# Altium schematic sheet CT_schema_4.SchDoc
size 578 x 363 mm
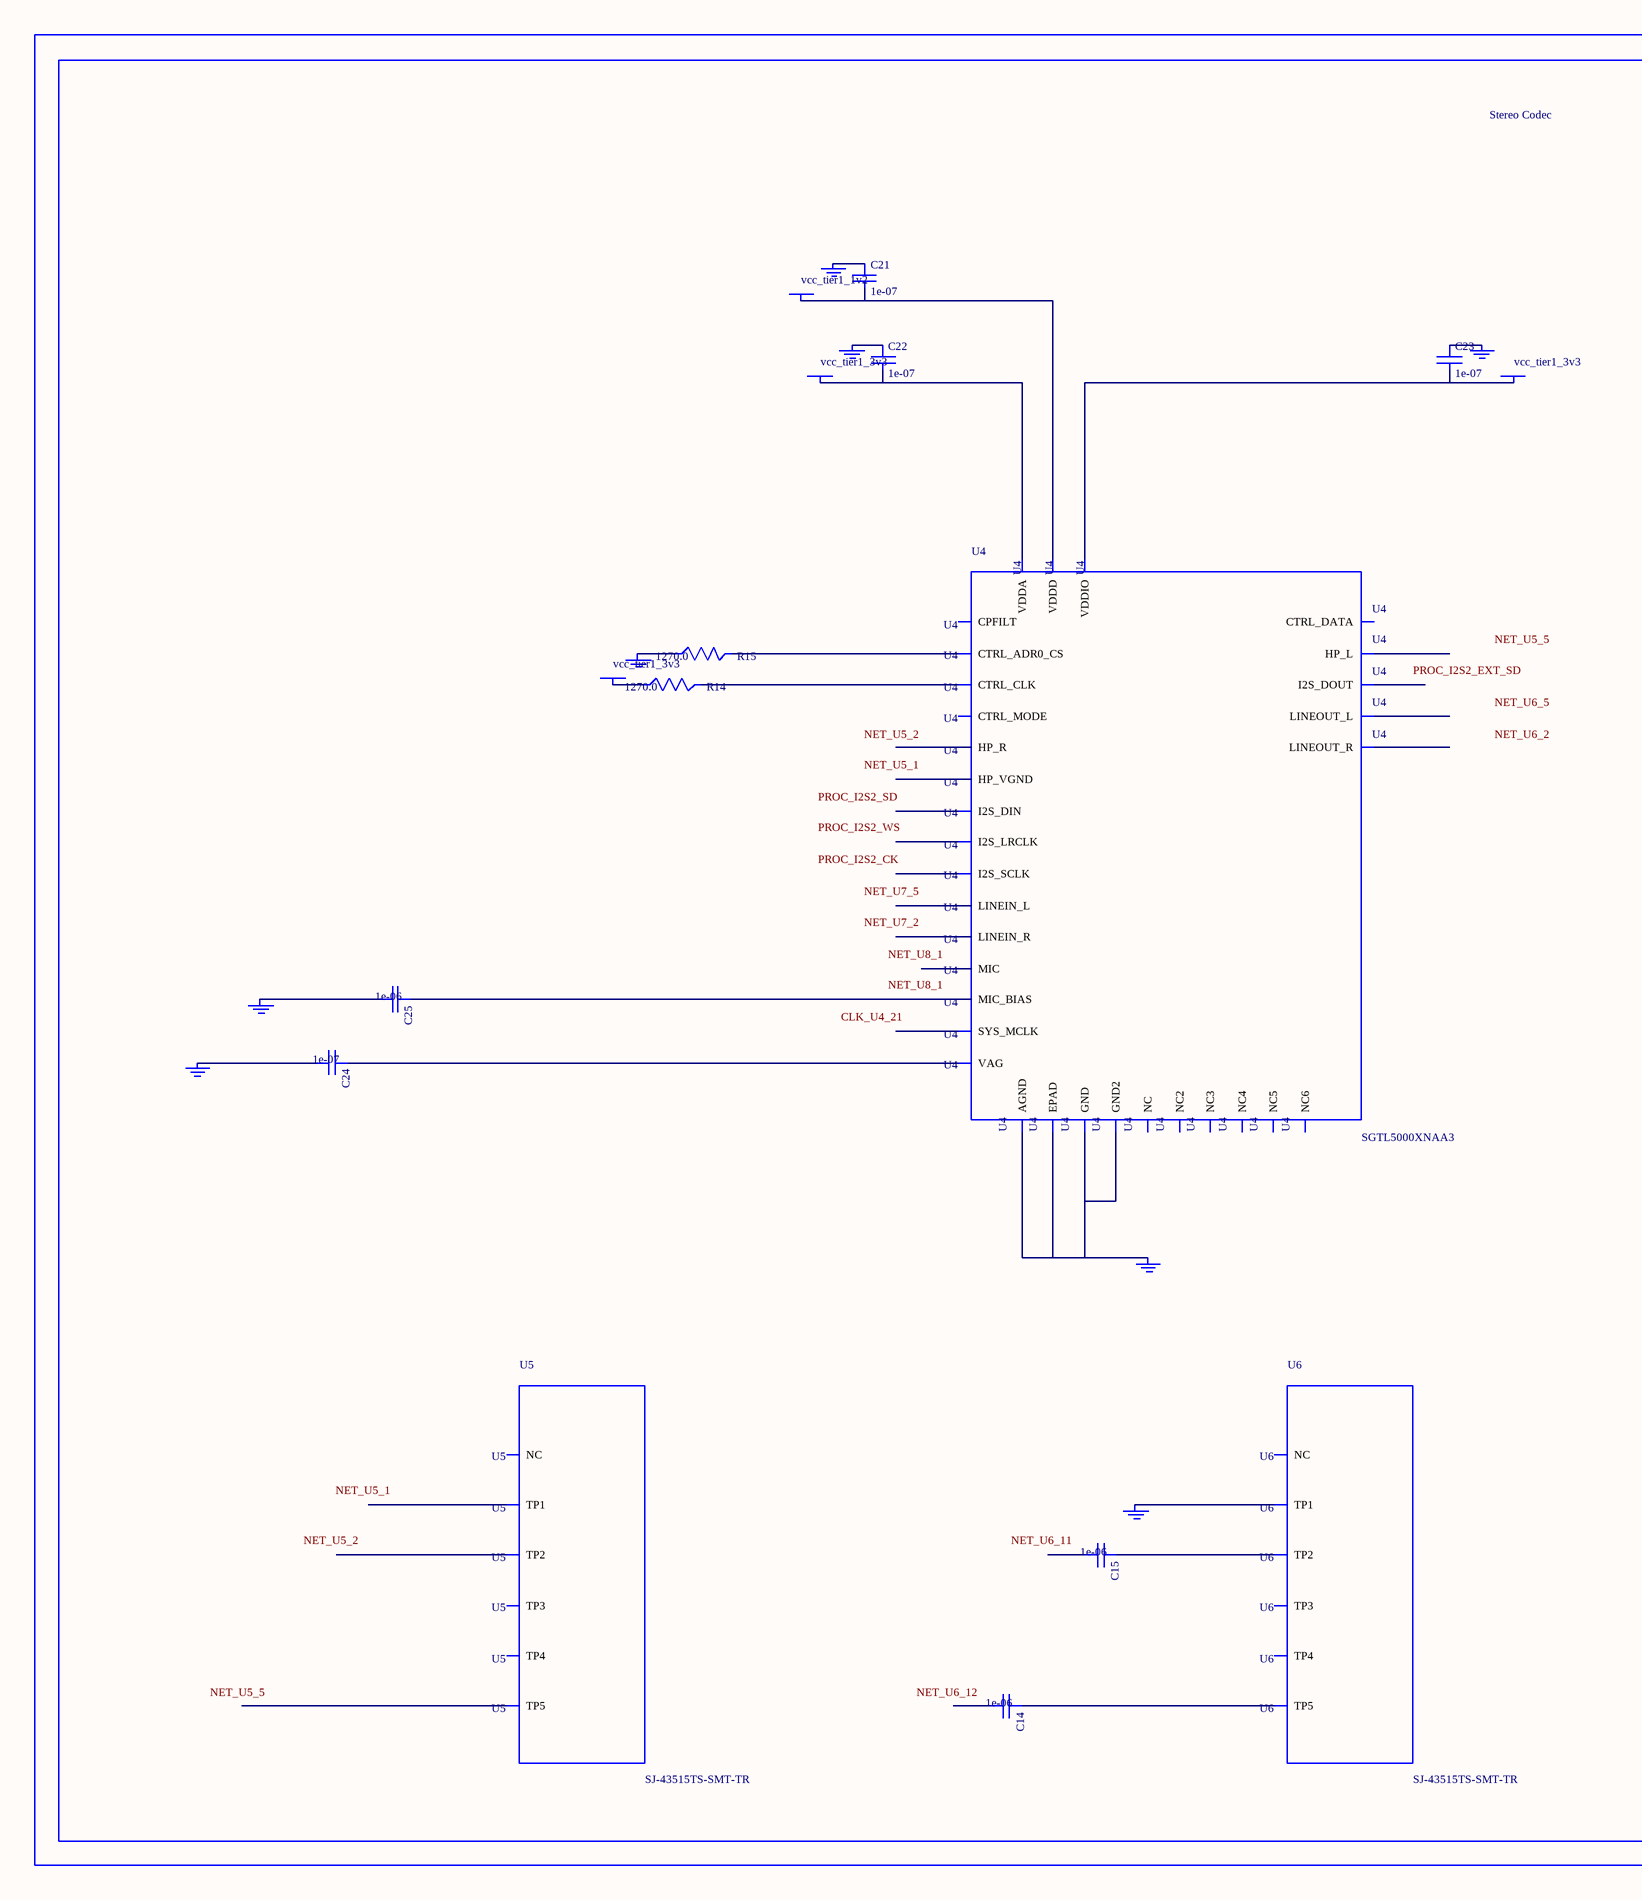
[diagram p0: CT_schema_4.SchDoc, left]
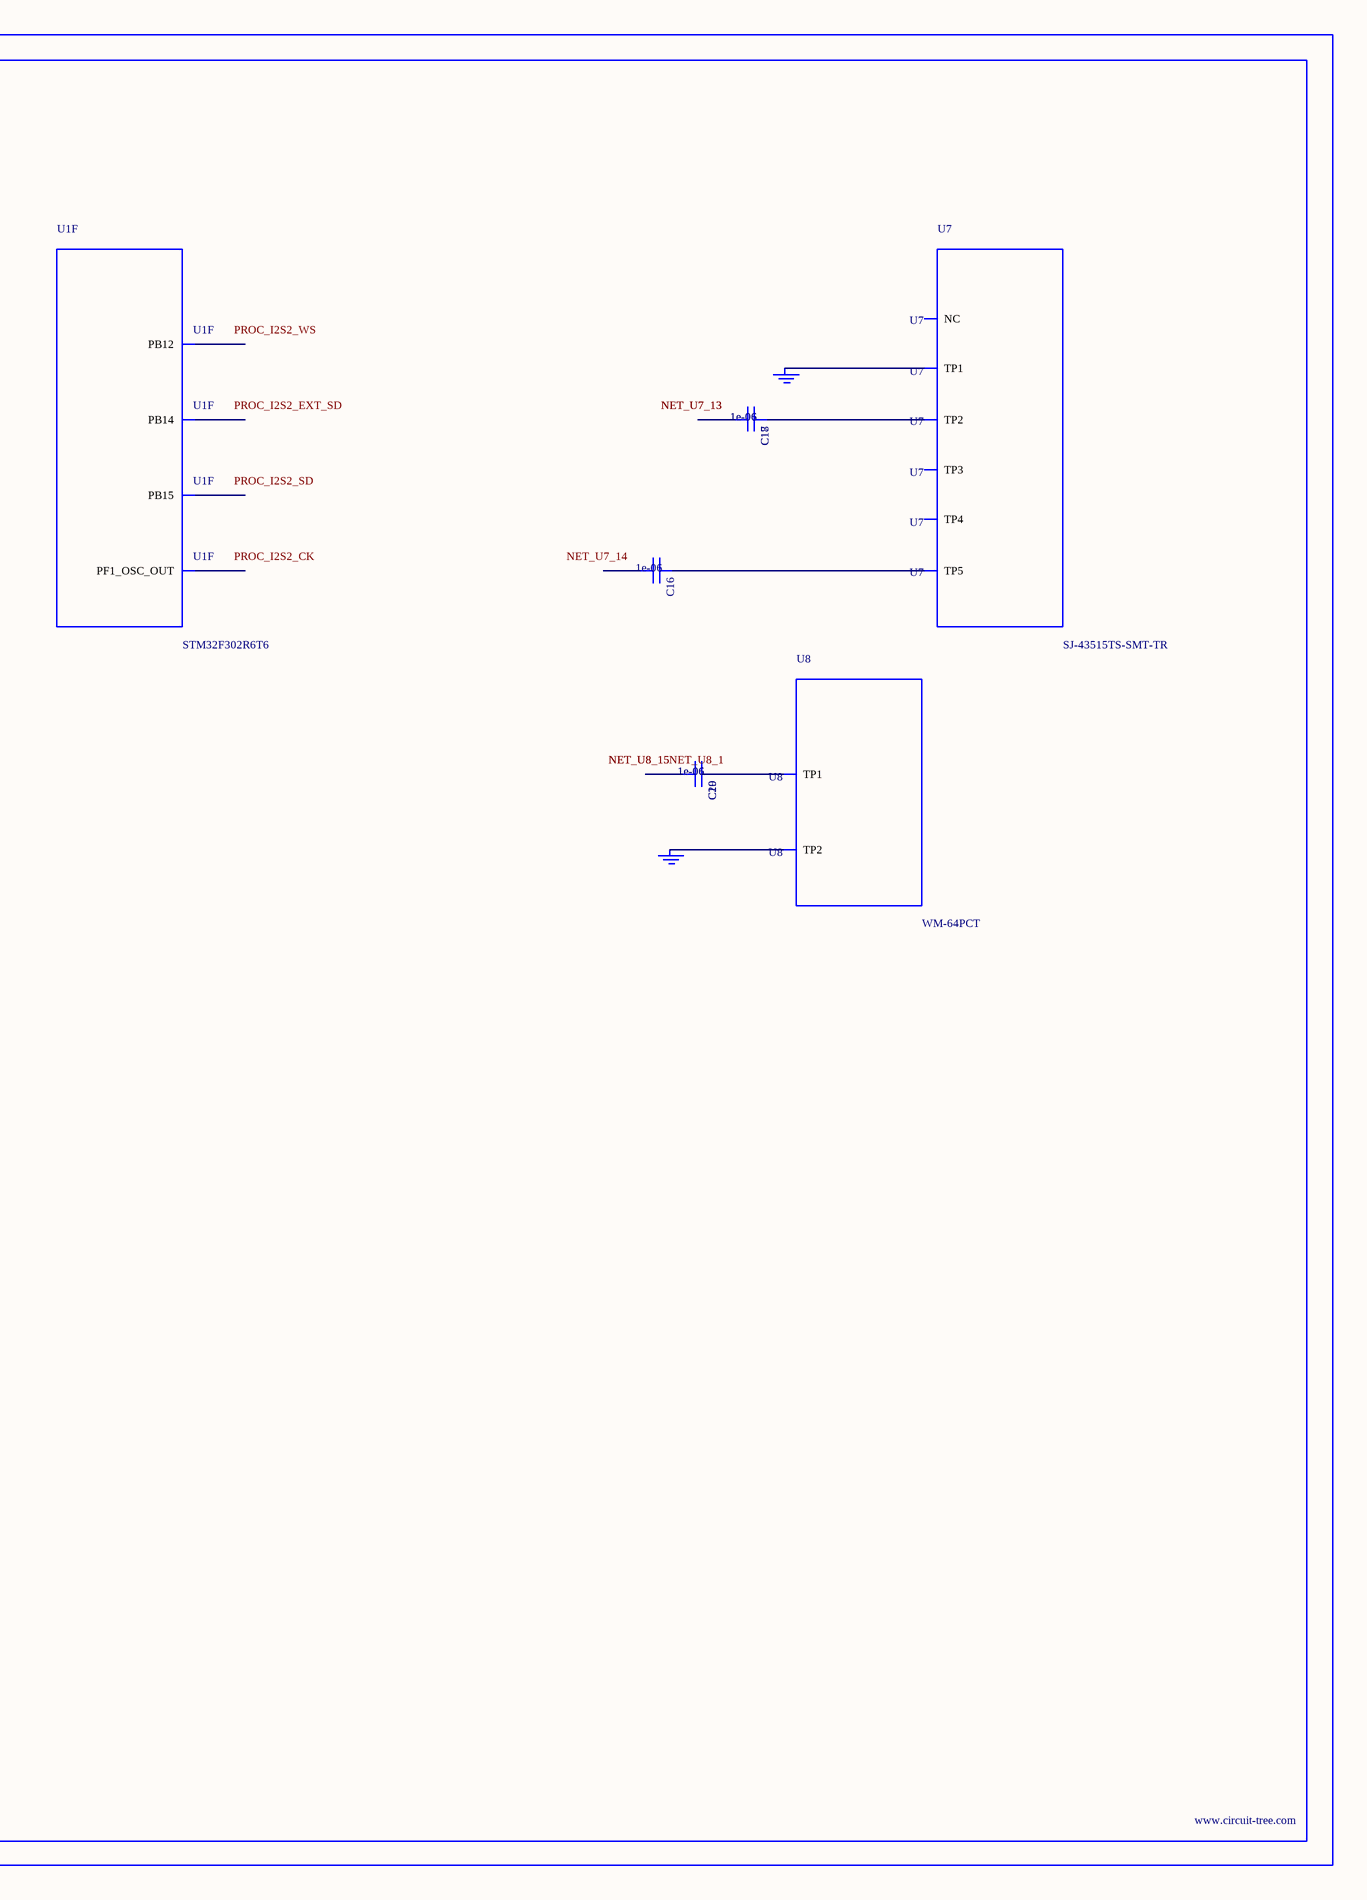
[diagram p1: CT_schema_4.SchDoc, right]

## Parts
BORDER3  (no value)
C14  1e-06  [C0603]
C15  1e-06  [C0603]
C16  1e-06  [C0603]
C17  1e-06  [C0603]
C18  1e-06  [C0603]
C19  1e-06  [C0603]
C20  1e-06  [C0603]
C21  1e-07  [C0402]
C22  1e-07  [C0402]
C23  1e-07  [C0402]
C24  1e-07  [C0402]
C25  1e-06  [C0603]
GND_INSTANCE_3_0  (no value)
GND_INSTANCE_3_1  (no value)
GND_INSTANCE_3_2  (no value)
GND_INSTANCE_3_3  (no value)
GND_INSTANCE_3_4  (no value)
GND_INSTANCE_3_5  (no value)
GND_INSTANCE_3_6  (no value)
GND_INSTANCE_3_7  (no value)
GND_INSTANCE_3_8  (no value)
GND_INSTANCE_3_9  (no value)
GND_INSTANCE_3_10  (no value)
POWER_INSTANCE_3_0  vcc_tier1_3v3
POWER_INSTANCE_3_1  vcc_tier1_3v3
POWER_INSTANCE_3_2  vcc_tier1_3v3
POWER_INSTANCE_3_3  vcc_tier1_1v2
R14  1270.0  [R0603]
R15  1270.0  [R0603]
U1  STM32F302R6T6  [LQFP64]  (part F of 7)
U4  SGTL5000XNAA3  [QFN-32]
U5  SJ-43515TS-SMT-TR  [SJ-43515TS-SMT-TR]
U6  SJ-43515TS-SMT-TR  [SJ-43515TS-SMT-TR]
U7  SJ-43515TS-SMT-TR  [SJ-43515TS-SMT-TR]
U8  WM-64PCT  [WM-64PC]

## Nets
NetC14_1: C14.1 U6.5(TP5)
NetC15_1: C15.1 U6.2(TP2)
NetC16_1: C16.1 U7.5(TP5)
NetC17_1: C17.1 C18.1 U7.2(TP2)
NetC17_2: C17.2 C18.2
NetC19_1: C19.1 C20.1 U8.1(TP1)
NetC19_2: C19.2 C20.2
NetC21_1: C21.1 GND_INSTANCE_3_5.0(GND)
NetC21_2: C21.2 POWER_INSTANCE_3_3.0(PWR) U4.30(VDDD)
NetC22_1: C22.1 GND_INSTANCE_3_1.0(GND)
NetC22_2: C22.2 POWER_INSTANCE_3_0.0(PWR) U4.5(VDDA)
NetC23_1: C23.1 GND_INSTANCE_3_4.0(GND)
NetC23_2: C23.2 POWER_INSTANCE_3_1.0(PWR) U4.20(VDDIO)
NetC24_1: C24.1 U4.10(VAG)
NetC24_2: C24.2 GND_INSTANCE_3_2.0(GND)
NetC25_1: C25.1 U4.16(MIC_BIAS)
NetC25_2: C25.2 GND_INSTANCE_3_3.0(GND)
NetGND_INSTANCE_3_0_0: GND_INSTANCE_3_0.0(GND) U4.1(GND) U4.3(GND2) U4.7(AGND) U4.EXP(EPAD)
NetGND_INSTANCE_3_6_0: GND_INSTANCE_3_6.0(GND) R15.1
NetGND_INSTANCE_3_7_0: GND_INSTANCE_3_7.0(GND) U6.1(TP1)
NetGND_INSTANCE_3_8_0: GND_INSTANCE_3_8.0(GND) GND_INSTANCE_3_9.0(GND) U7.1(TP1)
NetGND_INSTANCE_3_10_0: GND_INSTANCE_3_10.0(GND) U8.2(TP2)
NetPOWER_INSTANCE_3_2_0: POWER_INSTANCE_3_2.0(PWR) R14.1
NetR14_2: R14.2 U4.29(CTRL_CLK)
NetR15_2: R15.2 U4.31(CTRL_ADR0_CS)

Not connected (* = marked no-connect by the designer): C14 2; C15 2; C16 2; U1 6(PF1_OSC_OUT) 33(PB12) 35(PB14) 36(PB15); U4 2(HP_R) 4(HP_VGND) 6(HP_L) 8(NC) 9(NC2) 11(LINEOUT_R) 12(LINEOUT_L) 13(LINEIN_R) 14(LINEIN_L) 15(MIC) 17(NC3) 18(CPFILT) 19(NC4) 21(SYS_MCLK) 22(NC5) 23(I2S_LRCLK) 24(I2S_SCLK) 25(I2S_DOUT) 26(I2S_DIN) 27(CTRL_DATA) 28(NC6) 32(CTRL_MODE); U5 1(TP1) 2(TP2) 3(TP3) 4(TP4) 5(TP5) 6(NC); U6 3(TP3) 4(TP4) 6(NC); U7 3(TP3) 4(TP4) 6(NC)

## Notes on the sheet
- Labels drawn without touching a wire or pin: CLK_U4_21, NET_U5_1, NET_U5_2, NET_U5_5, NET_U6_2, NET_U6_5, NET_U6_11, NET_U6_12, NET_U7_2, NET_U7_5, NET_U7_14, NET_U8_1, PROC_I2S2_CK, PROC_I2S2_EXT_SD, PROC_I2S2_SD, PROC_I2S2_WS

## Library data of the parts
BORDER3 = BORDER_PAGE3
C14-C20 C25 = C0603C105K3RACTU
C21-C24 = C0402C104K3RACTU
GND_INSTANCE_3_0-GND_INSTANCE_3_10 = GND
POWER_INSTANCE_3_0-POWER_INSTANCE_3_3 = PWR
R14 R15 = RC0603FR-071K27L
